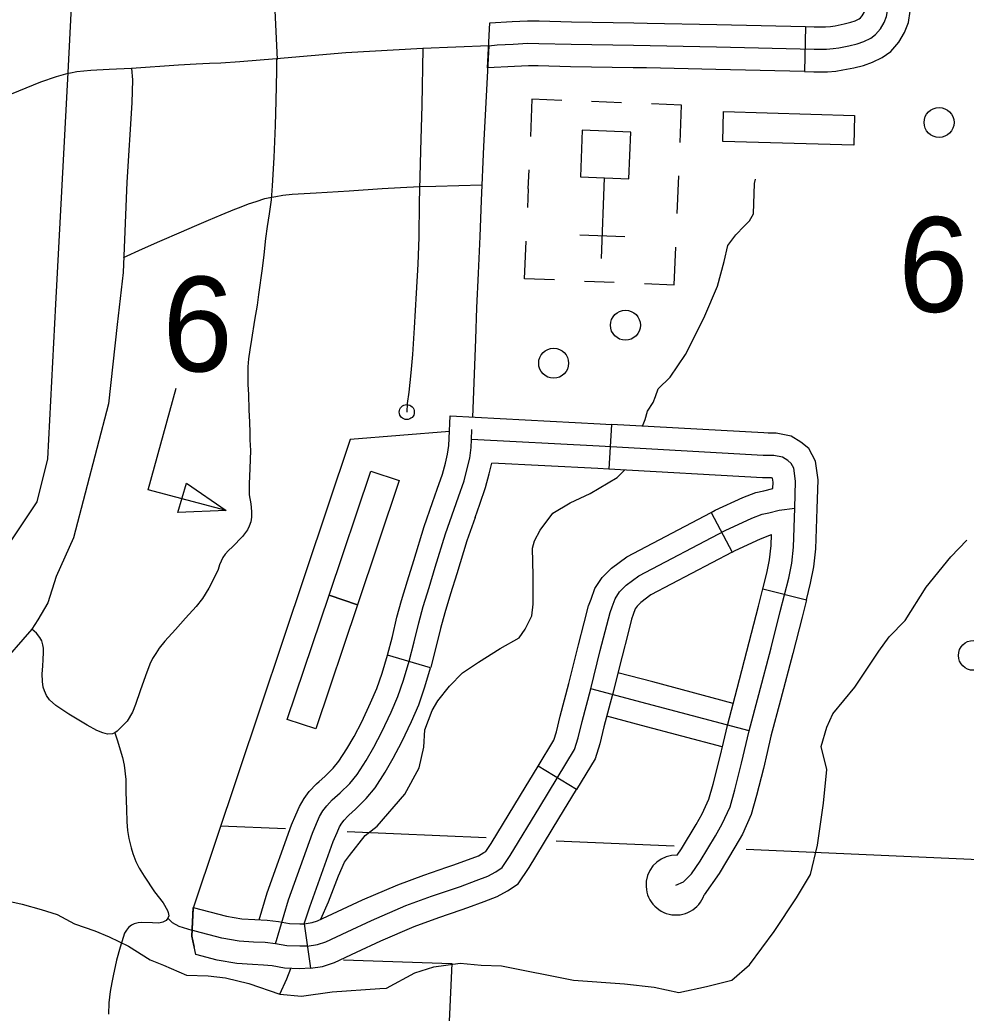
# Model space of a CAD drawing. Extents: x 653372 to 905732, y 627442 to 787275.
# Drawn here: x 690999 to 694158, y 757607 to 760924 of the extents above; entities that cross this region are included whole.
import ezdxf

# ---------------------------------------------------------------- set-up
doc = ezdxf.new("R2010")
doc.units = 0
for name, color, linetype in [('31', 7, 'Continuous'), ('33', 7, 'Continuous'), ('35', 7, 'Continuous'), ('5', 7, 'Continuous'), ('56', 7, 'Continuous'), ('57', 7, 'Continuous'), ('6', 7, 'Continuous')]:
    doc.layers.add(name, color=color, linetype=linetype)

msp = doc.modelspace()

# ---------------------------------------------------------------- linework, layer by layer
at = {"layer": '31'}
for p, q in [((692560.9, 760763.6), (692568.9, 760914.3)), ((693622.1, 760901.7), (693618.6, 760751.7)), ((692974.1, 759573.2), (692965.7, 759423.4)), ((693307.4, 759279.5), (693377.3, 759146.8)), ((693479.8, 759023.8), (693625.2, 758987.2)), ((692370.4, 758760.6), (692226.3, 758802.4)), ((692857.9, 758354.2), (692729.7, 758432.1)), ((692729.7, 758432.1), (692729.7, 758432.1)), ((691948.1, 757905.2), (691969.4, 757756.7))]:
    msp.add_line(p, q, dxfattribs=at)
for points in [[(692564.8, 760837.9), (692592.5, 760840.5), (692646.4, 760843.5), (692695.7, 760846), (692731.5, 760845.6), (692839.5, 760842.9), (693047.8, 760839.5), (693324.6, 760833.8), (693650.7, 760826), (693691.9, 760826.1), (693714.6, 760828.1), (693733.9, 760830.8), (693767.3, 760837.8), (693794.8, 760844.3), (693816.9, 760852.2), (693839.9, 760863.5), (693856.1, 760875), (693872.6, 760893.8), (693885.2, 760915.3), (693893.1, 760935), (693896.5, 760959.5), (693898.8, 761057.4), (693908, 761190.5)], [(693618.6, 760751.7), (693649.9, 760751), (693695.3, 760751.1), (693723.1, 760753.5), (693746.8, 760756.9), (693783.6, 760764.6), (693816.2, 760772.3), (693846.3, 760783.1), (693878.2, 760798.8), (693906.6, 760818.8), (693933.7, 760849.7), (693952.8, 760882.2), (693966.2, 760915.6), (693971.4, 760953.5), (693973.8, 761054), (693979.8, 761141)], [(693622.1, 760901.7), (693651.6, 760901), (693688.6, 760901.1), (693706, 760902.6), (693721, 760904.7), (693751.1, 760911), (693773.4, 760916.3), (693787.6, 760921.4), (693801.5, 760928.2), (693805.7, 760931.2), (693811.6, 760937.9), (693817.7, 760948.4), (693820.1, 760954.4), (693821.7, 760965.5), (693823.9, 761060.9), (693830.1, 761151.3)], [(692568.9, 760914.3), (692642.4, 760918.4), (692694.2, 760921.1), (692732.9, 760920.6), (692841, 760917.9), (693049.2, 760914.4), (693094, 760913.5)], [(693094, 760913.5), (693326.3, 760908.8), (693622.1, 760901.7)], [(693091, 760763.6), (693046.4, 760764.5), (692837.9, 760767.9), (692730.1, 760770.6), (692697.1, 760771), (692650.4, 760768.6), (692560.9, 760763.6)], [(693618.6, 760751.7), (693323, 760758.8), (693091, 760763.6)], [(691160, 760744.7), (691120.9, 760734.4), (691068.4, 760715.9), (690970.5, 760676)], [(692377.5, 759312.1), (692393, 759356.5), (692410.7, 759406.6), (692420.2, 759443.9), (692427.3, 759473.6), (692431.1, 759502.4), (692432.3, 759526.4), (692435.4, 759601.9)], [(692435.4, 759601.9), (692937.1, 759575.3), (692974.1, 759573.2)], [(693498, 759544.5), (693483.3, 759544.7), (692974.1, 759573.2)], [(691852.7, 757838.9), (691896.2, 757985.3), (691975.9, 758208.1), (691990.2, 758240.2), (691999.8, 758263.5), (692011.4, 758282.4), (692023.7, 758299.7), (692042, 758319.1), (692068.6, 758342.7), (692100.5, 758374.2), (692125, 758403.7), (692155, 758450.8), (692180.6, 758495), (692207.9, 758546.4), (692238.5, 758612), (692261.5, 758664.3), (692280.3, 758719.5), (692298.7, 758782.6), (692315.6, 758846.7), (692331.1, 758910.6), (692345.6, 758964.5), (692365.4, 759029), (692386, 759096.4), (692420.8, 759208.3), (692463.7, 759331.6), (692482.5, 759384.7), (692493, 759425.9), (692501.2, 759460), (692505.8, 759495.6), (692507.2, 759523), (692508.6, 759555.8)], [(693625.2, 758987.2), (693639.4, 759043.4), (693650.2, 759097.9), (693656.9, 759157.2), (693661.5, 759291.1), (693664.5, 759388), (693656, 759450.5), (693633.6, 759492.2), (693606.5, 759513.8), (693573.9, 759534.1), (693524.4, 759544.2), (693498, 759544.5)], [(693586.6, 759293.5), (693589.3, 759384), (693583.5, 759427), (693574.8, 759443.1), (693563.1, 759452.4), (693545.6, 759463.3), (693516.4, 759469.3), (693480.7, 759469.8), (692933, 759500.4), (692507.2, 759523)], [(692519.2, 759262.8), (692534.5, 759306.8), (692554.3, 759362.9), (692565.8, 759407.9), (692574.6, 759444.3)], [(692965.7, 759423.4), (692928.9, 759425.5), (692574.6, 759444.3)], [(693496.2, 759394.6), (693478.1, 759394.8), (692965.7, 759423.4)], [(693513.5, 759359), (693514.1, 759380.1), (693512.3, 759393.6), (693508.3, 759394.4), (693496.2, 759394.6)], [(693307.4, 759279.5), (693320.9, 759286.6), (693413.4, 759329.1), (693456.4, 759345.9), (693483.6, 759351), (693513.5, 759359)], [(692226.3, 758802.4), (692226.4, 758802.7), (692242.9, 758865.1), (692258.4, 758929.2), (692273.5, 758985.3), (692293.7, 759051), (692314.4, 759118.5), (692349.6, 759231.8), (692377.5, 759312.1)], [(692470, 758030.1), (692523, 758049.9), (692561.8, 758064.3), (692588.1, 758079), (692609.2, 758093.1), (692635.9, 758133.7), (692734.9, 758296.1), (692851.3, 758487.9), (692863.6, 758526.7), (692876.3, 758581), (692905.2, 758689.8), (692937, 758818), (692969.8, 758944.8), (692976.6, 758964.1), (692986.5, 758991.1), (693001.6, 759014.5), (693023.6, 759036), (693065.5, 759067.2), (693354.1, 759219.3), (693442.8, 759260.1), (693477.1, 759273.5), (693500.2, 759277.8), (693534.2, 759286.9), (693586.6, 759293.5)], [(692883.4, 758910.4), (692898, 758966.8), (692906.1, 758989.5), (692918.9, 759024.7), (692943.2, 759062.2), (692974.7, 759093.2), (693025.4, 759130.8), (693307.4, 759279.5)], [(693189.8, 758034.8), (693214.5, 758045.9), (693241.1, 758071.7), (693270.7, 758114.6), (693321.7, 758198.9), (693344.3, 758238.8), (693370.4, 758296.3), (693386.1, 758352.7), (693408.8, 758442.2), (693434.1, 758549.8), (693466.6, 758671.6), (693507.1, 758826.9), (693538.1, 758948), (693566.2, 759059.9), (693576, 759109.4), (693582, 759162.7), (693586.6, 759293.5)], [(692519.2, 759262.8), (692492.1, 759184.9), (692457.7, 759074.2), (692437.1, 759007), (692417.7, 758943.8), (692403.8, 758892), (692388.3, 758828.3), (692370.9, 758762.6), (692370.4, 758760.6)], [(693377.3, 759146.8), (693387.3, 759152), (693472.1, 759191), (693508.5, 759205.2)], [(693479.8, 759023.8), (693493, 759076.3), (693501.8, 759121), (693507.2, 759168.3), (693508.5, 759205.2)], [(693377.3, 759146.8), (693105.6, 759003.6), (693072.4, 758978.9), (693060, 758966.7), (693054, 758957.5), (693047.2, 758938.7), (693041.6, 758922.8), (693028.6, 758872.9)], [(693348, 758511.4), (693361.4, 758568.1), (693394.1, 758690.7), (693434.5, 758845.6), (693465.4, 758966.5), (693479.8, 759023.8)], [(693625.2, 758987.2), (693610.8, 758929.6), (693579.7, 758808.2), (693539.1, 758652.4), (693506.9, 758531.5), (693494, 758476.9)], [(692729.7, 758432.1), (692782.5, 758519.1), (692791.2, 758546.6), (692803.5, 758599.1), (692832.5, 758708.4), (692864.3, 758836.5), (692883.4, 758910.4)], [(693028.6, 758872.9), (693009.7, 758799.6), (692977.8, 758671.1), (692949, 758562.8), (692936, 758506.8), (692920.1, 758456.7), (692857.9, 758354.2)], [(691998.4, 758380.6), (692017.3, 758397.4), (692045.2, 758425), (692064.3, 758448), (692090.9, 758489.7), (692115, 758531.4), (692140.8, 758579.9), (692170.2, 758643), (692191.6, 758691.6), (692208.8, 758742.1), (692226.3, 758802.4)], [(692098, 758268.5), (692119.8, 758287.9), (692155.9, 758323.4), (692185.8, 758359.5), (692219.1, 758411.8), (692246.2, 758458.7), (692275.1, 758513), (692306.8, 758581.1), (692331.4, 758637), (692351.9, 758696.9), (692370.4, 758760.6)], [(693381, 758641.6), (693112.7, 758713), (692995.8, 758743.6)], [(693434.1, 758549.8), (693093.6, 758640.5), (692905.2, 758689.8)], [(693344.4, 758496.1), (693074.5, 758568), (692958.5, 758598.3)], [(693193.5, 758134.8), (693207.7, 758155.3), (693257, 758236.8), (693277.4, 758272.8), (693299.7, 758322), (693313.7, 758372), (693335.9, 758460), (693348, 758511.4)], [(693494, 758476.9), (693481.6, 758424.4), (693458.6, 758333.5), (693441.1, 758270.6), (693411.3, 758204.7), (693386.4, 758161), (693333.7, 758073.8), (693284.4, 758002.3)], [(692424.9, 758094), (692444.8, 758100.8), (692496.9, 758120.2), (692530.3, 758132.6), (692548.8, 758143), (692554.8, 758147), (692572.5, 758173.9), (692670.8, 758335.1), (692729.7, 758432.1)], [(691798.1, 757918.6), (691824.9, 758008.6), (691906.3, 758236), (691921.2, 758269.6), (691932.7, 758297.6), (691948.9, 758323.8), (691965.6, 758347.4), (691989.8, 758373), (691998.4, 758380.6)], [(692473, 757952), (692495.2, 757959.5), (692549.1, 757979.6), (692593.3, 757996), (692627.3, 758015), (692663.5, 758039.3), (692699.2, 758093.6), (692798.9, 758257.1), (692857.9, 758354.2)], [(691948.1, 757905.2), (691967.5, 757961.9), (692045.6, 758180.2), (692059.2, 758210.7), (692066.8, 758229.4), (692073.9, 758240.9), (692081.8, 758252), (692094.3, 758265.2), (692098, 758268.5)], [(691948.1, 757905.2), (691975.7, 757909.2), (691993.3, 757915), (692060, 757946.9), (692143.1, 757985.1), (692260.7, 758036), (692348.5, 758068.1), (692424.9, 758094)], [(691958.7, 757830.9), (691993, 757835.9), (692021.4, 757845.3), (692091.8, 757879), (692173.7, 757916.6), (692288.5, 757966.3), (692373.4, 757997.4), (692470, 758030.1)], [(691586.5, 757802.7), (691573, 757864.3), (691578.4, 757959.9), (691689.7, 757930.6), (691740.4, 757922), (691783.9, 757919.3), (691824.6, 757917.3), (691863.1, 757913.2), (691899.1, 757906.9), (691934.3, 757905.3), (691948.1, 757905.2)], [(691969.4, 757756.7), (692010.2, 757762.6), (692049.5, 757775.6), (692123.7, 757811.1), (692204.3, 757848.2), (692316.3, 757896.6), (692398.3, 757926.7), (692473, 757952)], [(691958.7, 757830.9), (691933.6, 757830.2), (691890.8, 757832.2), (691852.7, 757838.9), (691818.8, 757842.5), (691779.7, 757844.4), (691731.9, 757847.4), (691673.8, 757857.2), (691585.2, 757880.6), (691574, 757883.9)], [(691969.4, 757756.7), (691932.9, 757755.2), (691882.6, 757757.6), (691842.2, 757764.6), (691813, 757767.7), (691775.6, 757769.6), (691723.3, 757772.7), (691658, 757783.8), (691586.5, 757802.7)]]:
    msp.add_lwpolyline(points, dxfattribs=at)
msp.add_arc((693189.8, 758034.8), 100, 87.8905, 340.9925, dxfattribs=at)
at = {"layer": '33'}
for points in [[(692564.8, 760837.9), (692344.7, 760828.4), (692088.1, 760814), (691856.2, 760793.6), (691733.4, 760784), (691670.5, 760780), (691632.1, 760778.2), (691588.5, 760776.6), (691528.6, 760772.5), (691372.5, 760761.6), (691298.1, 760758.7), (691236.7, 760755), (691190.1, 760750.5), (691168.6, 760746.3), (691160, 760744.7)], [(692344.7, 760828.4), (692341.1, 760639.4), (692337.3, 760486.7), (692332.7, 760313.9), (692331.6, 760198), (692328.2, 760108.7), (692322.2, 760011.1), (692315.7, 759895.9), (692310, 759806.7), (692304.3, 759745), (692297.8, 759680.6), (692292.1, 759642.6), (692291.2, 759614.3)], [(692564.8, 760837.9), (692547.1, 760500.9), (692539.9, 760320.8), (692534.9, 760200.8), (692529, 760077.9), (692523.4, 759962.9), (692521, 759857.9), (692513.6, 759682.8), (692510.2, 759597.9)], [(691856.2, 760793.6), (691855.7, 760754.4), (691854.2, 760654.1), (691851.3, 760571.1), (691847.7, 760464.2), (691841.5, 760369.9), (691838.3, 760323.4), (691834.5, 760299.4), (691832, 760276.9), (691825.1, 760233.9), (691819.7, 760193.9), (691814.3, 760139), (691808.1, 760093.7), (691796.4, 760007.2), (691791.2, 759971.5), (691782.2, 759921.8), (691772.4, 759856.7), (691767.6, 759822.6), (691762.9, 759792.5), (691761, 759765.9), (691760.2, 759739.2), (691760.7, 759706.5), (691762.4, 759673), (691763.8, 759622.2), (691766, 759580.2), (691766.9, 759545.7), (691767.7, 759522), (691769.1, 759485.8), (691767.7, 759426.4), (691764.7, 759374.6), (691765.4, 759337.7), (691770.6, 759307.9), (691772.8, 759281.9), (691773, 759263.2), (691770.6, 759247.7), (691765.3, 759233.3), (691759.7, 759221.3), (691742.9, 759199.3), (691709.1, 759164.2), (691696, 759151.8), (691685.1, 759140.1), (691676.5, 759128.2), (691666.4, 759104.4), (691661.8, 759089.1), (691648.1, 759060.6), (691629.8, 759025.9)], [(691372.5, 760761.6), (691375, 760724.3), (691372.7, 760647.5), (691356.6, 760381.8), (691343.8, 760080.3), (691324.6, 759907), (691294.9, 759641.6), (691178.3, 759194.1), (691120.1, 759065.4), (691092.9, 758977.8), (691059.5, 758920.2), (691039.7, 758889.7), (691009.5, 758855.2), (690956.8, 758794.8)], [(691345.9, 760130.1), (691408.6, 760159.1), (691466.5, 760184.8), (691539.3, 760216.7), (691582, 760235.3), (691628.9, 760255.6), (691671.5, 760272.8), (691717.2, 760292.2), (691732.5, 760297.9), (691763.2, 760310.2), (691788.8, 760317.9), (691817.5, 760327.4), (691833.6, 760331.2), (691854.2, 760334.9), (691877, 760338.5), (691908.3, 760341.8), (691988.1, 760346.9), (692098.4, 760353.1), (692209.2, 760361.5), (692270.5, 760364.9), (692334.4, 760368.1), (692387.9, 760368.5), (692542, 760372.8)], [(691629.8, 759025.9), (691609.3, 758991.9), (691587.8, 758965.1), (691552, 758926.3), (691518.6, 758887.9), (691483.2, 758849.5), (691464.1, 758825.6), (691453.1, 758808.6), (691442, 758791.7), (691433.2, 758772.7), (691418.5, 758733.6), (691401.6, 758683), (691385.9, 758637.6), (691375.4, 758612.4), (691357.6, 758582.1), (691341.3, 758565.7), (691324.6, 758548.9), (691316.2, 758542.7), (691308.6, 758539.5), (691292, 758538.9), (691276, 758543.2), (691256.3, 758551.3), (691224.1, 758568.4), (691162.9, 758606), (691119.4, 758634.7), (691098.5, 758653), (691088.1, 758667.6), (691081.4, 758683.6), (691077.6, 758695.7), (691074.8, 758714.6), (691073.4, 758740.6), (691076.3, 758765.3), (691077, 758788.6), (691078.8, 758811.1), (691078.2, 758825.4), (691075.9, 758837.5), (691072.5, 758850.8), (691066.4, 758861.1), (691054.5, 758876.4), (691039.7, 758889.7)], [(691316.2, 758542.7), (691324.1, 758519.9), (691341.9, 758461.1), (691347.2, 758435.4), (691352.9, 758387.4), (691353.5, 758345.2), (691355.1, 758288), (691356.5, 758246.2), (691359, 758217.2), (691363.5, 758190.4), (691371.2, 758158.6), (691376.2, 758140.3), (691386.3, 758113.3), (691397.7, 758090.8), (691414.6, 758064.7), (691449.1, 758012.2), (691477.3, 757974.9), (691492.3, 757949.6), (691494.7, 757943.5), (691496.3, 757932.2), (691493.8, 757924), (691488.3, 757916.3), (691476.5, 757910.6), (691463.2, 757908), (691442.2, 757908.2), (691404.7, 757910.1), (691394.5, 757909.1), (691380.5, 757905.1), (691372.1, 757900.4), (691362.4, 757892.8), (691355, 757883.6), (691349.1, 757873.7), (691343.8, 757859.2), (691333.8, 757827.1), (691322.3, 757783.5), (691311.4, 757732), (691306.2, 757709.5), (691301.2, 757679.6), (691296.6, 757641.3), (691295.1, 757603.4)], [(691493.8, 757924), (691507.8, 757909.5), (691530.3, 757897), (691574, 757883.9)]]:
    msp.add_lwpolyline(points, dxfattribs=at)
msp.add_circle((692291.2, 759614.3), 25, dxfattribs=at)
at = {"layer": '35'}
for points in [[(693078.2, 759567.4), (693086.7, 759589.9), (693095.1, 759617.9), (693114, 759645.9), (693121.2, 759666.2), (693130.7, 759692), (693170.7, 759730.7), (693221.1, 759806.2), (693246.7, 759856.5), (693286.6, 759936.1), (693328.6, 760035.4), (693350.5, 760117.1), (693362.6, 760170.7), (693389.2, 760206), (693417.1, 760235.2), (693435.6, 760252.6), (693448.3, 760276.2), (693452.4, 760377.7), (693455.4, 760392.7)], [(692004.5, 757920.3), (692030, 757978.7), (692062.9, 758065.4), (692083.3, 758111), (692100.3, 758133.5), (692152.5, 758200), (692192.4, 758231.8), (692284.9, 758337.9), (692332.6, 758426.5), (692348.1, 758495.1), (692351.4, 758553.5), (692375.8, 758617.3), (692394.8, 758649.8), (692433.8, 758699.4), (692477.1, 758743.1), (692530.7, 758779), (692602.6, 758824.9), (692666.7, 758860.5), (692686.5, 758889.6), (692708.8, 758934), (692713, 758972.9), (692712.9, 759069), (692711.1, 759160.2), (692717.8, 759184), (692736.9, 759219.5), (692779.1, 759276.7), (692836.7, 759310.8), (692903.7, 759341.9), (692993.1, 759396.2), (693017.9, 759420.5)], [(692223, 757690.6), (692318.1, 757741.9), (692381.1, 757761.7), (692469.2, 757773.9), (692539.4, 757767), (692607.2, 757765.4), (692847.6, 757717.4), (693017.8, 757704.6), (693117.2, 757693.9), (693199.1, 757676.1), (693291.7, 757696.4), (693376.6, 757716.8), (693435.7, 757768.7), (693517.6, 757879.4), (693592, 757992.3), (693638.4, 758069.5), (693662.4, 758168.5), (693681.9, 758307.9), (693693, 758420.7), (693674.2, 758498), (693693.4, 758562.6), (693713.9, 758606.1), (693787.1, 758695.1), (693867.4, 758815.4), (693901.5, 758864.3), (693954.9, 758918.3), (694025.3, 759029.3), (694106.9, 759130.4), (694160.4, 759186.3)], [(690972.2, 757978.9), (691007.5, 757971.1), (691070.2, 757952.9), (691124.3, 757936), (691181.8, 757905.5), (691249.2, 757881.4), (691297.7, 757862.2), (691361.9, 757830.3), (691433.9, 757784.7)], [(691433.9, 757784.7), (691479.5, 757767), (691555.9, 757733.3), (691628.2, 757731.4), (691686, 757724.6), (691763.3, 757706)], [(691867.5, 757670.3), (691891, 757721.4), (691904.1, 757756.5)], [(691763.3, 757706), (691867.5, 757670.3), (691940.1, 757663.3), (692042.2, 757678.5), (692200.6, 757689), (692223, 757690.6)]]:
    msp.add_lwpolyline(points, dxfattribs=at)
at = {"layer": '5'}
for points in [[(691669.8, 758233), (691885.7, 758223.3)], [(692091.6, 758214.1), (692556, 758193.4)], [(692789.9, 758182.9), (693183.5, 758165.3)], [(693424.2, 758154.6), (694977.6, 758085.2)]]:
    msp.add_lwpolyline(points, dxfattribs=at)
at = {"layer": '56'}
for p, q in [((691527.2, 759278.7), (691555.2, 759376.7)), ((691555.2, 759376.7), (691688.3, 759285.7)), ((691688.3, 759285.7), (691527.2, 759278.7))]:
    msp.add_line(p, q, dxfattribs=at)
for points in [[(693345.9, 760518.5), (693348.9, 760618.5), (693786.2, 760605.4), (693783.2, 760505.4)], [(692171.3, 759417.3), (692266, 759385.4), (692126.6, 758970.7), (692031.8, 759002.6)], [(692031.8, 759002.6), (692126.6, 758970.7), (691987.1, 758556.1), (691892.3, 758587.9)]]:
    msp.add_lwpolyline(points, close=True, dxfattribs=at)
msp.add_lwpolyline([(691688.3, 759285.7), (691428.3, 759354.5), (691521.6, 759694.4)], dxfattribs=at)
for centre in [(694067.9, 760581.6), (693021, 759904.5), (692781.4, 759777.6), (694182.8, 758801.9)]:
    msp.add_circle(centre, 50, dxfattribs=at)
at = {"layer": '57'}
for p, q in [((693007.9, 760647.5), (692907.9, 760651.5)), ((692696.6, 760359.7), (692699.2, 760423)), ((692940.6, 760127.3), (692951.3, 760396.3)), ((693193.8, 760278.1), (693198.8, 760403)), ((692696.6, 760359.7), (692694.2, 760298.1)), ((693018.5, 760199.2), (692868.6, 760205.2)), ((692883.9, 760052), (692983.8, 760048))]:
    msp.add_line(p, q, dxfattribs=at)
for points in [[(692808.6, 760655.5), (692708.6, 760659.5), (692703.6, 760534.6)], [(693203.2, 760514.6), (693208.2, 760639.5), (693108.3, 760643.5)], [(692784.6, 760055.9), (692684.6, 760059.9), (692689.6, 760184.8)], [(693084.3, 760043.9), (693184.2, 760039.9), (693189.2, 760164.8)]]:
    msp.add_lwpolyline(points, dxfattribs=at)
msp.add_lwpolyline([(692877, 760555.4), (692870.8, 760399.5), (693032.5, 760393.1), (693038.7, 760549)], close=True, dxfattribs=at)
at = {"layer": '6'}
for points in [[(690883, 759053.9), (691057, 759315), (691093, 759457.9), (691119.5, 759974.4), (691160.2, 760748.8), (691172.2, 760968.2), (691851, 760955.7), (691858.8, 760792)], [(692433.5, 759549.8), (692101.7, 759523.3), (691577.8, 757958), (691573, 757864.3), (691581.1, 757827.2)], [(692080.4, 757784.9), (692441.9, 757772.9), (692336.5, 755499.6), (690429.1, 755614.1), (690424.7, 755497.3), (690354.2, 753803.5), (690338.7, 753445.3)]]:
    msp.add_lwpolyline(points, dxfattribs=at)

# ---------------------------------------------------------------- texts
at = {"layer": '56'}
for p in [(693927.4, 759952.7), (691471.3, 759753.9)]:
    msp.add_text('6', height=316.8, rotation=358.28, dxfattribs=at).set_placement(p)

doc.saveas('drawing.dxf')
